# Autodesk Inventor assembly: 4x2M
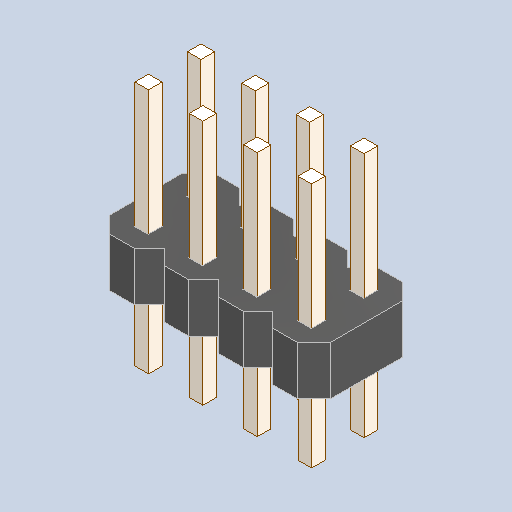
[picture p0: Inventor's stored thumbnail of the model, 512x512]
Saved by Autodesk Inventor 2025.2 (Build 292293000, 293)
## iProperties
Created: 2025-04
Part Number: 4x2M
Description: PART--DESC
Document SubType Name: Assembly
Designer: BennF
Author: BennF
Revision Number: NONE
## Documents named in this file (3)
- C:\Users\BennF\Nextcloud\Benutzer\CNC JarBeRi\existing parts\Electronics\RepRap A4988 Shied (USE WITHOUT ARDUINO)\reprap-a4988-1.snapshot.1\RepRap\RepRap\4x2M_1.iam
- C:\Users\BennF\Nextcloud\Benutzer\CNC JarBeRi\existing parts\Electronics\RepRap A4988 Shied (USE WITHOUT ARDUINO)\reprap-a4988-1.snapshot.1\RepRap\RepRap\4x2M Geometry.ipt
- C:\Users\BennF\Nextcloud\Benutzer\CNC JarBeRi\existing parts\Electronics\RepRap A4988 Shied (USE WITHOUT ARDUINO)\reprap-a4988-1.snapshot.1\RepRap\RepRap\pin8.ipt
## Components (2 placed, 2 different names)
1. 4x2M Geometry
2. pin8
